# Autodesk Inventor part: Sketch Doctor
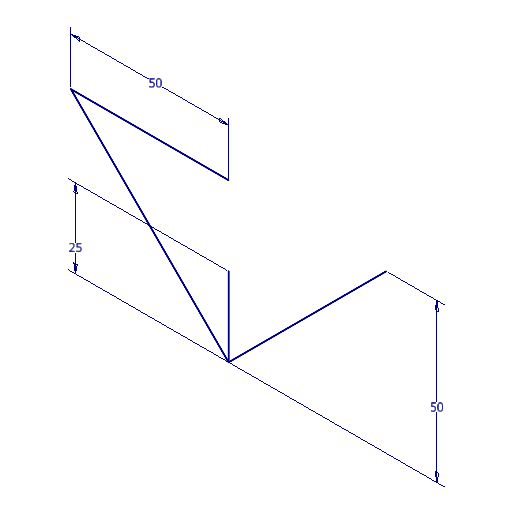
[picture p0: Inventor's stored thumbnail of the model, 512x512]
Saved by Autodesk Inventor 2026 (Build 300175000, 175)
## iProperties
Created: 2022-10
Part Number: Sketch Doctor
Material: Generic
Document SubType Name: Modeling
Designer: lbp
Density: 1 g/cm^3
Appearance: Default
Author: lbp
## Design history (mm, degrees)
sketch "Sketch1"
  geometry: L1 (0, 0)-(-50, 50); L2 (-50, 50)-(0, 50); L3 (0, 0)-(0, 25); L4 (0, 0)-(50, 50)
  constraints: 8 end point, 1 horizontal, 1 horizontal alignment, 1 perpendicular, 1 vertical, 1 vertical alignment
  dimensions: "d0" = 50 dimension on L1.start L1.end L1 L2.end L2 L3.end L3 L4.end L4; "d0" = 50 horizontal distance of L1.start L4.end; "d1" = 25 distance of L1.start L3.end; "d2" = 50 distance of L1.end L2.end
